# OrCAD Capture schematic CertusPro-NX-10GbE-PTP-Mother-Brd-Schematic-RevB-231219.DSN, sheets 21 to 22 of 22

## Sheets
21 20_PS-1V8,1VLDO: size A3; title: 20_PS-1V8,1VLDO
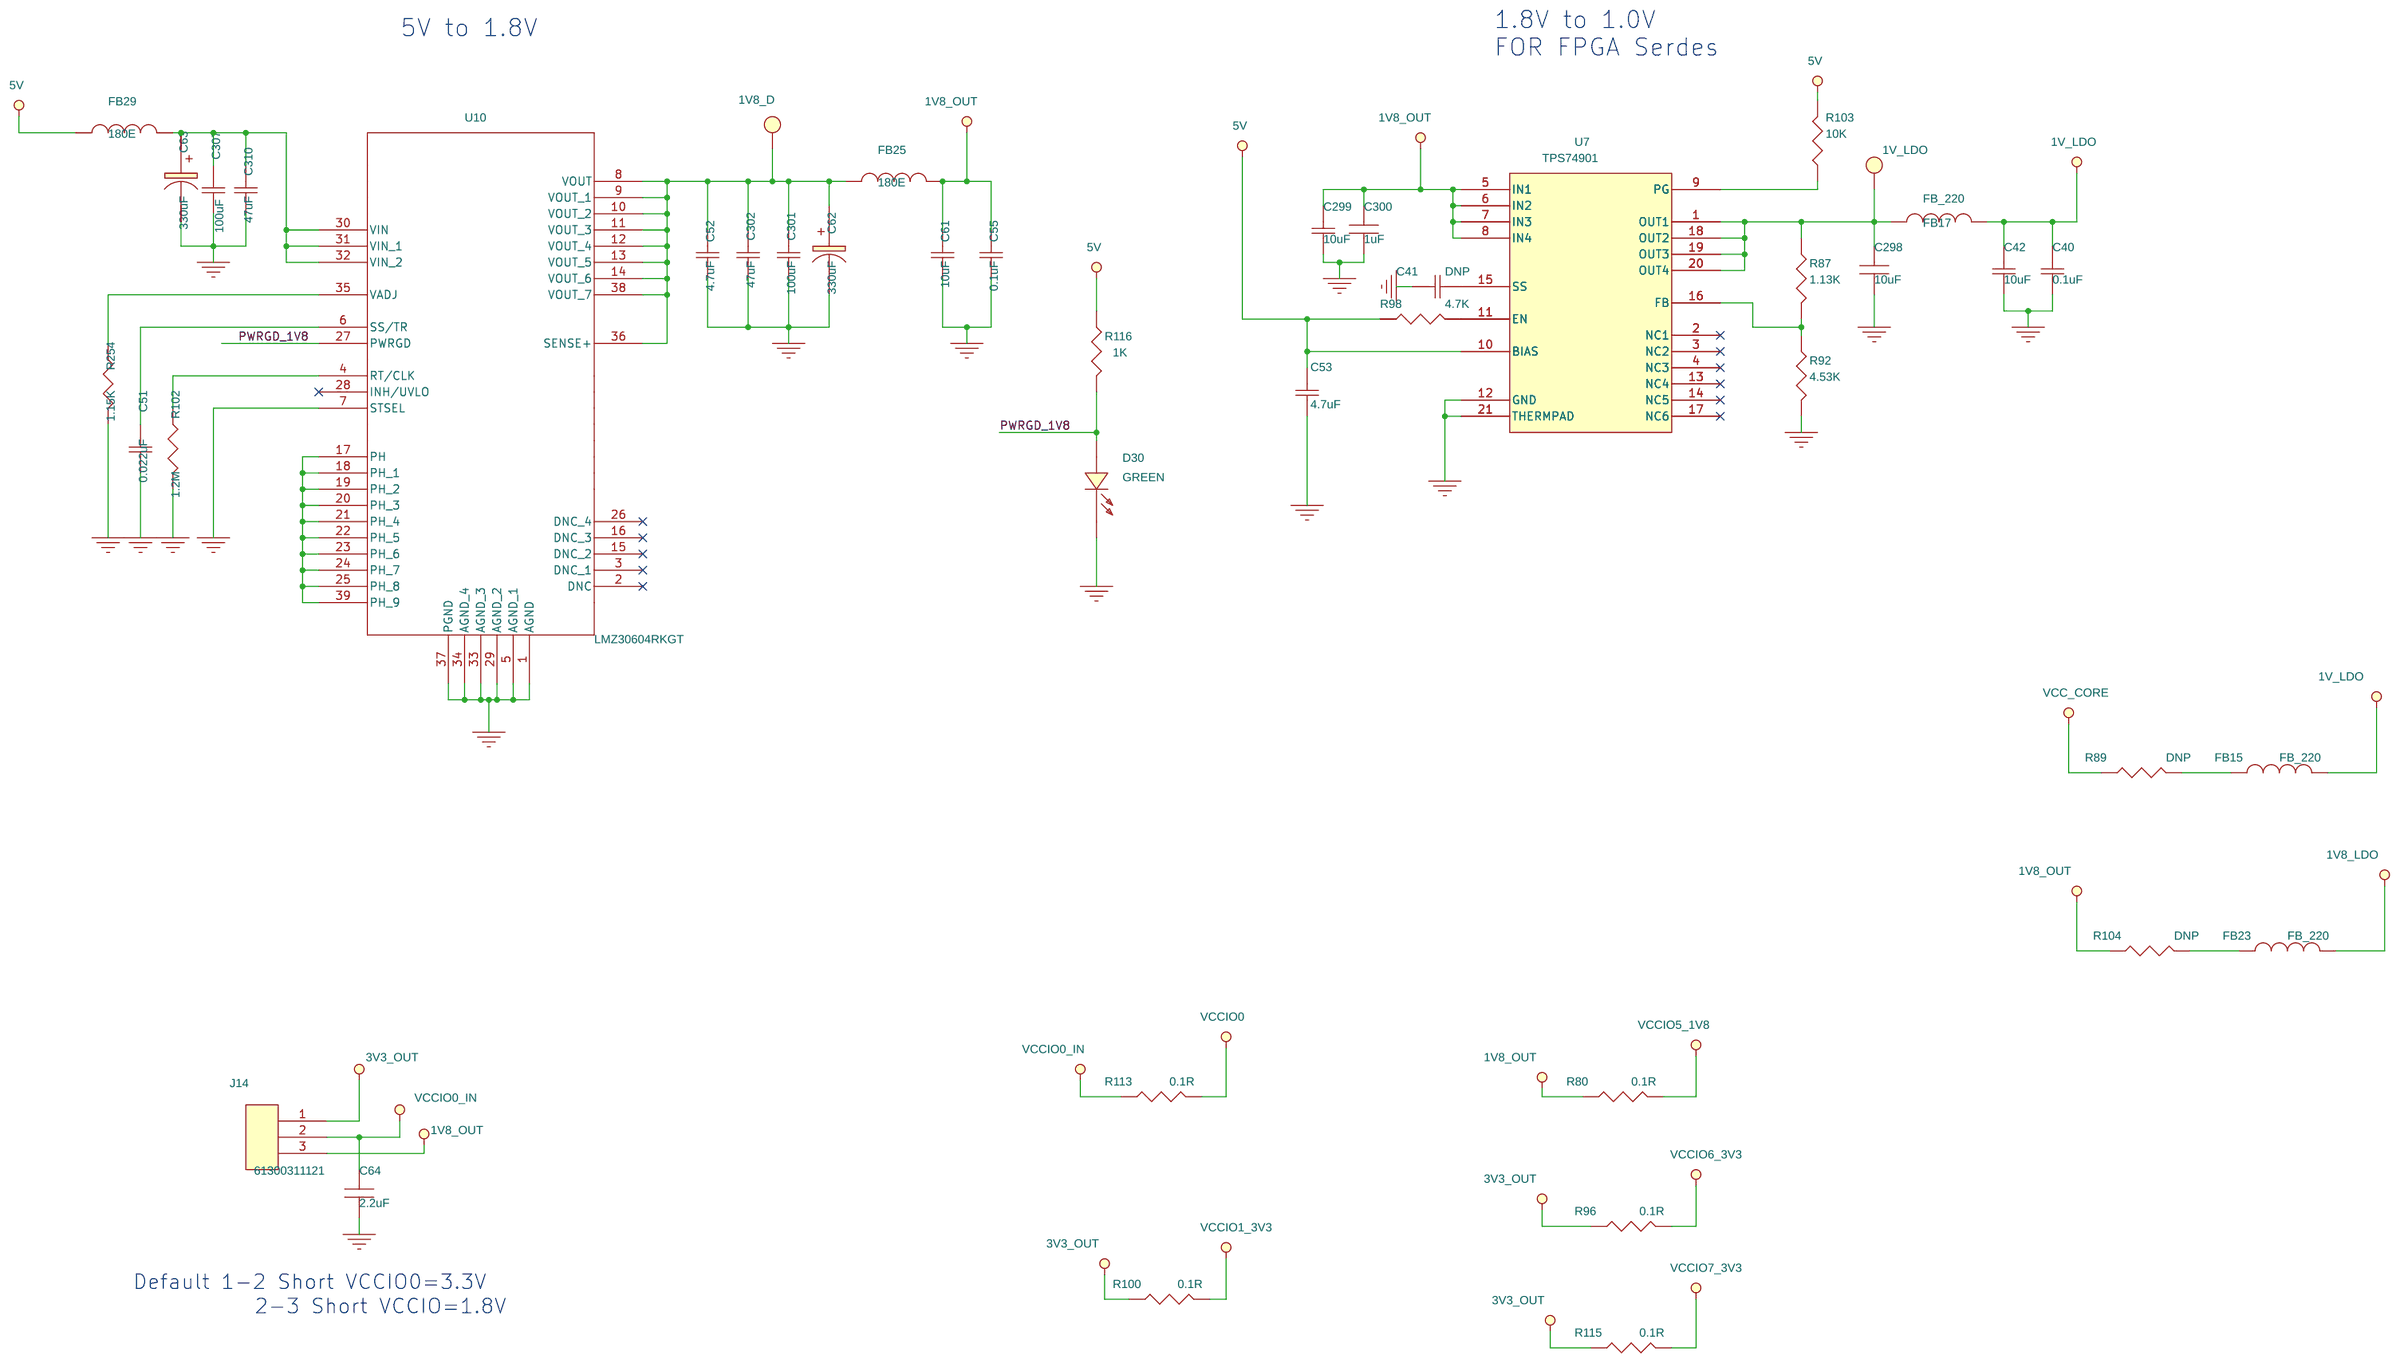
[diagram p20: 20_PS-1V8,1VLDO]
22 09_FPGA_B1-Led,7Seg,FTDI_Ctrl: size A3; title: 09_FPGA_B1-Led,7Seg,FTDI_Ctrl
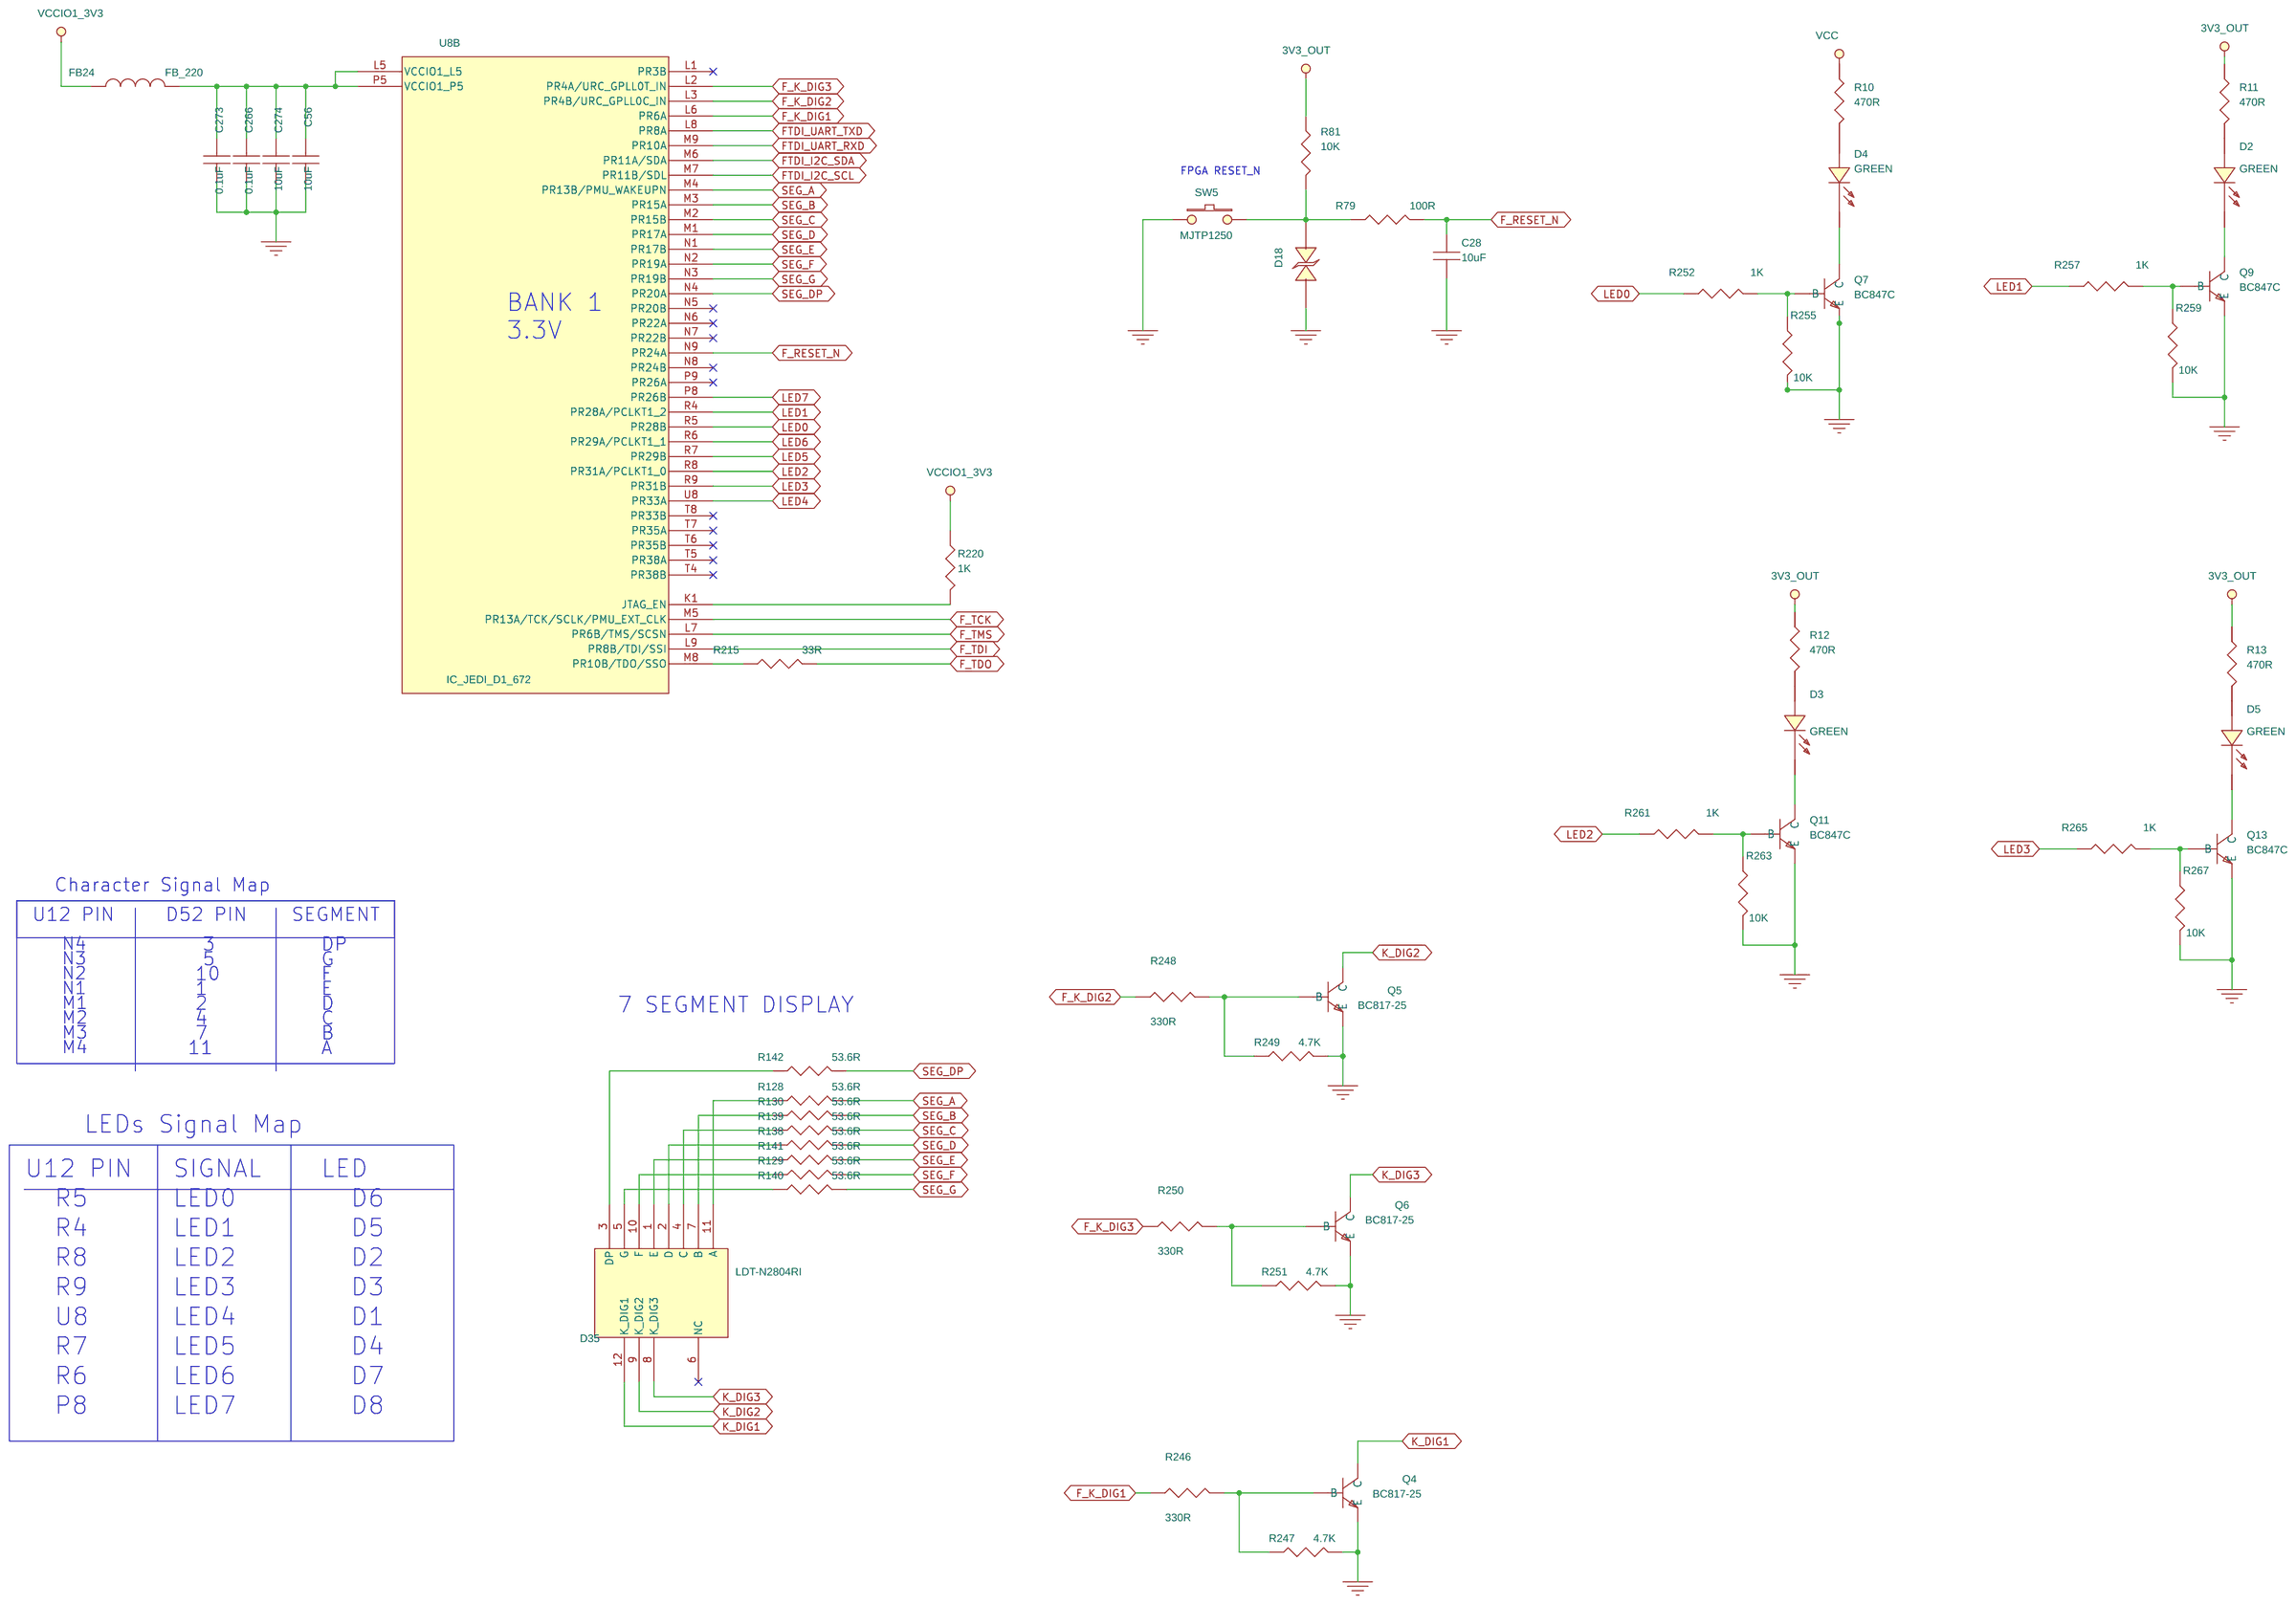
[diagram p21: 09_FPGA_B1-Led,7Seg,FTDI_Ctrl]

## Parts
sheet 09_FPGA_B1-Led,7Seg,FTDI_Ctrl
C28  10uF  [cap0603]
C56  10uF  [cap0603]
C266  0.1uF  [cap0402]
C273  0.1uF  [cap0402]
C274  10uF  [cap0603]
D2  GREEN  [led_0603]
D3  GREEN  [led_0603]
D4  GREEN  [led_0603]
D5  GREEN  [led_0603]
D18  DIODE_SUPPRESSOR ESD 30VDC 0402  [ESD0402]
D35  LDT-N2804RI  [display_12P-PTH]
FB24  FB_220  [FB0603]
Q4  BC817-25  [SOT23-3]
Q5  BC817-25  [SOT23-3]
Q6  BC817-25  [SOT23-3]
Q7  BC847C  [sot23_3]
Q9  BC847C  [sot23_3]
Q11  BC847C  [sot23_3]
Q13  BC847C  [sot23_3]
R10  470R  [res0402]
R11  470R  [res0402]
R12  470R  [res0402]
R13  470R  [res0402]
R79  100R  [res0402]
R81  10K  [res0603]
R128  53.6R  [res0402]
R129  53.6R  [res0402]
R130  53.6R  [res0402]
R138  53.6R  [res0402]
R139  53.6R  [res0402]
R140  53.6R  [res0402]
R141  53.6R  [res0402]
R142  53.6R  [res0402]
R215  33R  [res0402]
R220  1K  [res0603]
R246  330R  [res0603]
R247  4.7K  [res0603]
R248  330R  [res0603]
R249  4.7K  [res0603]
R250  330R  [res0603]
R251  4.7K  [res0603]
R252  1K  [res0603]
R255  10K  [res0402]
R257  1K  [res0603]
R259  10K  [res0402]
R261  1K  [res0603]
R263  10K  [res0402]
R265  1K  [res0603]
R267  10K  [res0402]
SW5  MJTP1250  [SW_TH2]
sheet 19_PS-5V,1V
U8  IC_JEDI_D1_672  [FPGA-672]  (sections A,B,C,D,E,F,G,H,I,J,K,L,M,N,O)
sheet 20_PS-1V8,1VLDO
1V8_D  1V8_D  [TP_50]
1V_LDO  1V_LDO  [TP_50]
C40  0.1uF  [cap0402]
C41  DNP  [cap0603]
C42  10uF  [cap0603]
C51  0.022uF  [cap0603]
C52  4.7uF  [cap0603]
C53  4.7uF  [cap0402]
C55  0.1uF  [cap0402]
C61  10uF  [cap0603]
C62  330uF  [cap2917]
C63  330uF  [cap2917]
C64  2.2uF  [cap0402]
C298  10uF  [cap0603]
C299  10uF  [cap0603]
C300  1uF  [cap0603]
C301  100uF  [cap1206]
C302  47uF  [cap1206]
C307  100uF  [cap1206]
C310  47uF  [cap1206]
D30  GREEN  [led_0603]
FB15  FB_220  [FB0603]
FB17  FB_220  [FB0603]
FB23  FB_220  [FB0603]
FB25  180E  [FB0805]
FB29  180E  [FB0805]
J14  61300311121  [conn_header_3pos]
R80  0.1R  [res0603]
R87  1.13K  [res0402]
R89  DNP  [res0603]
R92  4.53K  [res0402]
R96  0.1R  [res0603]
R98  4.7K  [res0603]
R100  0.1R  [res0603]
R102  1.2M  [res0603]
R103  10K  [res0603]
R104  DNP  [res0603]
R113  0.1R  [res0603]
R115  0.1R  [res0603]
R116  1K  [res0603]
R254  1.15K  [res0603]
U7  TPS74901  [vqfn_20]
U10  LMZ30604RKGT  [RKG39]

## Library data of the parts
C28 C56 C274 C298 = C_10uf_CER_25V_0603: CAP CER 10UF 25V X5R 0603
C266 C273 = C_0.1uF_50V_CER_0402
D2-D5 D30 = LED_GREEN_0603
D18 = DIODE_SUPPRESSOR_ESD_30VDC_0402
D35 = 7SEG_LDT-N2804RI__12-DIP
FB15 FB17 FB23 FB24 = FB__220E_0603
Q4-Q6 = TRANS_NPN_45V_0.8A_SOT-23
Q7 Q9 Q11 Q13 = TRANS_NPN_BC847C_SOT-23
R10-R13 = R_470R_0402_1%_0.063W
R79 = R_100R_0402
R81 R103 = R_10K_0603
R128-R130 R138-R142 = R_53.6R_0402
R215 = R_33R_0402
R116 R220 R252 R257 R261 R265 = R_1K_0603
R246 R248 R250 = R_330R_0603
R98 R247 R249 R251 = R_4.7K_0603
R255 R259 R263 R267 = R_10K_0402_5%_0.1W_Au
SW5 = SWITCH_TACTILE_SPST-NO_0.05A_12
U8 = IC_JEDI_D1_672
1V8_D 1V_LDO = TP_SMD: Component Type: Test Point
C40 C55 = C_0.1uF_25V_Cer-0402
C41 C51 = C_0.022uF_50V_CER_0603
C42 C61 C299 = C_10uF_16V_Cer_0603
C52 = C_4.7uF_25V_CER_0603
C53 = C_4.7uF_10V_Cer_0402
C62 C63 = C_330uF_10V_Tan_2917: MSL: 1
C64 = C_2.2uF_CER_25V_0402
C300 = C_1uF_50V_CER_0603
C301 C307 = C_100uF_10V_Cer_1206
C302 C310 = C_47uF_1206_25V
FB25 FB29 = FB_180E_0805: ROHS/NON-ROHS: ROHS
J14 = J_CONN_Header_3_POS_VERT_2.54mm
R80 R96 R100 R113 R115 = R_0.1R_0603
R87 = R_1.13K_0402
R89 R104 = R_0R_0603
R92 = R_4.53K_0402: ROHS/NON-ROHS: ROHS; TOLERANCE: ±1%
R102 = R_1.2M_0603
R254 = R_1.15K_0603
U7 = VR_TPS74901RGWR_0
U10 = VR_LMZ30604RKGT_39-B1QFN

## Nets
1V8_LDO: FB23.2 ; also on sheet 8 15 17 18 20
1V8_OUT: C55.1 C61.1 C299.1 C300.1 FB25.2 J14.3 R80.1 R104.1 U7.5(IN1) U7.6(IN2) U7.7(IN3) U7.8(IN4) ; also on sheet 9 14 16
1V_LDO: C40.1 C42.1 FB15.2 FB17.2 ; also on sheet 18
3V3_OUT: J14.1 R10.1 R11.1 R12.1 R13.1 R81.1 R96.1 R100.1 R115.1 ; also on sheet 2 6 7 8 12 13 14 16 17 18
5V: C53.1 FB29.1 R98.1 R103.2 R116.1 U7.10(BIAS) ; also on sheet 1 8 16 20
GND: C28.2 C40.2 C41.1 C42.2 C51.2 C52.2 C53.2 C55.2 C56.2 C61.2 C62.2 C63.2 C64.2 C266.2 C273.2 C274.2 C298.2 C299.2 C300.2 C301.2 C302.2 C307.2 C310.2 D18.2(A2) D30.K Q4.2(E) Q5.2(E) Q6.2(E) Q7.2(E) Q9.2(E) Q11.2(E) Q13.2(E) R92.2 R102.2 R247.2 R249.2 R251.2 R254.2 R255.2 R259.2 R263.2 R267.2 SW5.1 U7.12(GND) U7.21(THERMPAD) U10.1(AGND) U10.5(AGND_1) U10.7(STSEL) U10.29(AGND_2) U10.33(AGND_3) U10.34(AGND_4) U10.37(PGND) ; also on sheet 1 2 6 7 8 9 12 13 14 15 16 17 18 19 20
VCC_CORE: R89.1 ; also on sheet 20
VCCIO0: R113.2 ; also on sheet 12
VCCIO0_IN: C64.1 J14.2 R113.1
VCCIO1_3V3: FB24.1 R100.2 R220.1
VCCIO5_1V8: R80.2 ; also on sheet 13
VCCIO6_3V3: R96.2 ; also on sheet 6
VCCIO7_3V3: R115.2 ; also on sheet 19
F_K_DIG1: R246.1 U8.L6(PR6A)
F_K_DIG2: R248.1 U8.L3(PR4B/URC_GPLL0C_IN)
F_K_DIG3: R250.1 U8.L2(PR4A/URC_GPLL0T_IN)
F_RESET_N: C28.1 R79.2 U8.N9(PR24A)
F_TCK: U8.M5(PR13A/TCK/SCLK/PMU_EXT_CLK) ; also on sheet 16
F_TDI: U8.L9(PR8B/TDI/SSI) ; also on sheet 16
F_TDO: R215.2 ; also on sheet 16
F_TMS: U8.L7(PR6B/TMS/SCSN) ; also on sheet 16
FTDI_I2C_SCL: U8.M7(PR11B/SDL) ; also on sheet 16
FTDI_I2C_SDA: U8.M6(PR11A/SDA) ; also on sheet 16
FTDI_UART_RXD: U8.M9(PR10A) ; also on sheet 16
FTDI_UART_TXD: U8.L8(PR8A) ; also on sheet 16
K_DIG1: D35.12(K_DIG1) Q4.3(C)
K_DIG2: D35.9(K_DIG2) Q5.3(C)
K_DIG3: D35.8(K_DIG3) Q6.3(C)
LED0: R252.1 U8.R5(PR28B)
LED1: R257.1 U8.R4(PR28A/PCLKT1_2)
LED2: R261.1 U8.R8(PR31A/PCLKT1_0)
LED3: R265.1 U8.R9(PR31B)
LED4: U8.U8(PR33A) ; also on sheet 14
LED5: U8.R7(PR29B) ; also on sheet 14
LED6: U8.R6(PR29A/PCLKT1_1) ; also on sheet 14
LED7: U8.P8(PR26B) ; also on sheet 14
PWRGD_1V8: D30.A R116.2 U10.27(PWRGD)
SEG_A: R128.2 U8.M4(PR13B/PMU_WAKEUPN)
SEG_B: R130.2 U8.M3(PR15A)
SEG_C: R139.2 U8.M2(PR15B)
SEG_D: R138.2 U8.M1(PR17A)
SEG_DP: R142.2 U8.N4(PR20A)
SEG_E: R141.2 U8.N1(PR17B)
SEG_F: R129.2 U8.N2(PR19A)
SEG_G: R140.2 U8.N3(PR19B)
N14094890: R102.1 U10.4(RT/CLK)
N14094906: R254.1 U10.35(VADJ)
N14094938: C51.1 U10.6(SS/TR)
N14094986: C63.1 C307.1 C310.1 FB29.2 U10.30(VIN) U10.31(VIN_1) U10.32(VIN_2)
N14095190: 1V8_D.1 C52.1 C62.1 C301.1 C302.1 FB25.1 U10.8(VOUT) U10.9(VOUT_1) U10.10(VOUT_2) U10.11(VOUT_3) U10.12(VOUT_4) U10.13(VOUT_5) U10.14(VOUT_6) U10.36(SENSE+) U10.38(VOUT_7)
N14095504: U10.17(PH) U10.18(PH_1) U10.19(PH_2) U10.20(PH_3) U10.21(PH_4) U10.22(PH_5) U10.23(PH_6) U10.24(PH_7) U10.25(PH_8) U10.39(PH_9)
N14191909: D35.11(A) R128.1
N14191948: D35.7(B) R130.1
N14191955: D35.4(C) R139.1
N14191962: D35.2(D) R138.1
N14191991: D35.1(E) R141.1
N14191998: D35.10(F) R129.1
N14192022: D35.5(G) R140.1
N14281909: D35.3(DP) R142.1
N17524588: C56.1 C266.1 C273.1 C274.1 FB24.2 U8.L5(VCCIO1) U8.P5(VCCIO1)
N17775113: 1V_LDO.1 C298.1 FB17.1 R87.1 U7.1(OUT1) U7.18(OUT2) U7.19(OUT3) U7.20(OUT4)
N17783849: FB15.1 R89.2
N17784428: FB23.1 R104.2
N18236205: D18.1(A1) R79.1 R81.2 SW5.2
N18811078: R103.1 U7.9(PG)
N18811355: R87.2 R92.1 U7.16(FB)
N18882072: R215.1 U8.M8(PR10B/TDO/SSO)
N18882074: R220.2 U8.K1(JTAG_EN)
N19363673: Q6.1(B) R250.2 R251.1
N19364796: Q5.1(B) R248.2 R249.1
N19364975: Q4.1(B) R246.2 R247.1
N19778349: D4.K Q7.3(C)
N19778371: Q7.1(B) R252.2 R255.1
N19779855: D2.K Q9.3(C)
N19779880: Q9.1(B) R257.2 R259.1
N19781146: D3.K Q11.3(C)
N19781171: Q11.1(B) R261.2 R263.1
N19781784: D5.K Q13.3(C)
N19781809: Q13.1(B) R265.2 R267.1
N20207185: D4.A R10.2
N20207187: D3.A R12.2
N20207188: D2.A R11.2
N20207189: D5.A R13.2
N20207529: C41.2 U7.15(SS)
N20207530: R98.2 U7.11(EN)

Not connected (* = marked no-connect by the designer): D35 6(NC)*; U7 2(NC1)* 3(NC2)* 4(NC3)* 13(NC4)* 14(NC5)* 17(NC6)*; U8 L1(PR3B)* N5(PR20B)* N6(PR22A)* N7(PR22B)* N8(PR24B)* P9(PR26A)* T4(PR38B)* T5(PR38A)* T6(PR35B)* T7(PR35A)* T8(PR33B)*; U10 2(DNC)* 3(DNC_1)* 15(DNC_2)* 16(DNC_3)* 26(DNC_4)* 28(INH/UVLO)*

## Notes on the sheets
sheet 21
- 5V to 1.8V
- 1.8V to 1.0V
  FOR FPGA Serdes
- Default 1-2 Short VCCIO0=3.3V
- 2-3 Short VCCIO=1.8V
sheet 22
- FPGA RESET_N
- BANK 1
  3.3V
- Character Signal Map
- U12 PIN
- D52 PIN
- SEGMENT
- N4
- 3
- DP
- N3
- 5
- G
- N2
- 10
- F
- N1
- 1
- E
- M1
- 2
- D
- 7 SEGMENT DISPLAY
- M2
- 4
- C
- M3
- M4
- 11
- 7
- A
- B
- LEDs Signal Map
- U12 PIN
- SIGNAL
- LED
- R5
- LED0
- D6
- R4
- LED1
- D5
- R8
- LED2
- D2
- R9
- LED3
- D3
- U8
- LED4
- D1
- R7
- LED5
- D4
- R6
- LED6
- D7
- P8
- LED7
- D8
